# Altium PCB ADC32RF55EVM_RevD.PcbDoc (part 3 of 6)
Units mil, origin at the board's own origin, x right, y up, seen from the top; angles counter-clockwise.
Board outline 4190 x 2750 mil, 14 copper layers (Top Copper, Layer 2 (GND1), Layer 3 (PWR1), Layer 4 (GND2, Layer 5 (PWR2), Layer 6 (GND3), Layer 7 (SIG1), Layer 8 (GND4), Layer 9 (GND5), Layer 10 (SIG2), Layer 11 (GND6), Layer 12 (PWR3), Layer 13 (GND7), Bottom Copper), stack 58.6 mil thick; 427 components, 558 nets, 1902 pads, 1008 vias.
Unrouted connection lines stored in the file: 51.
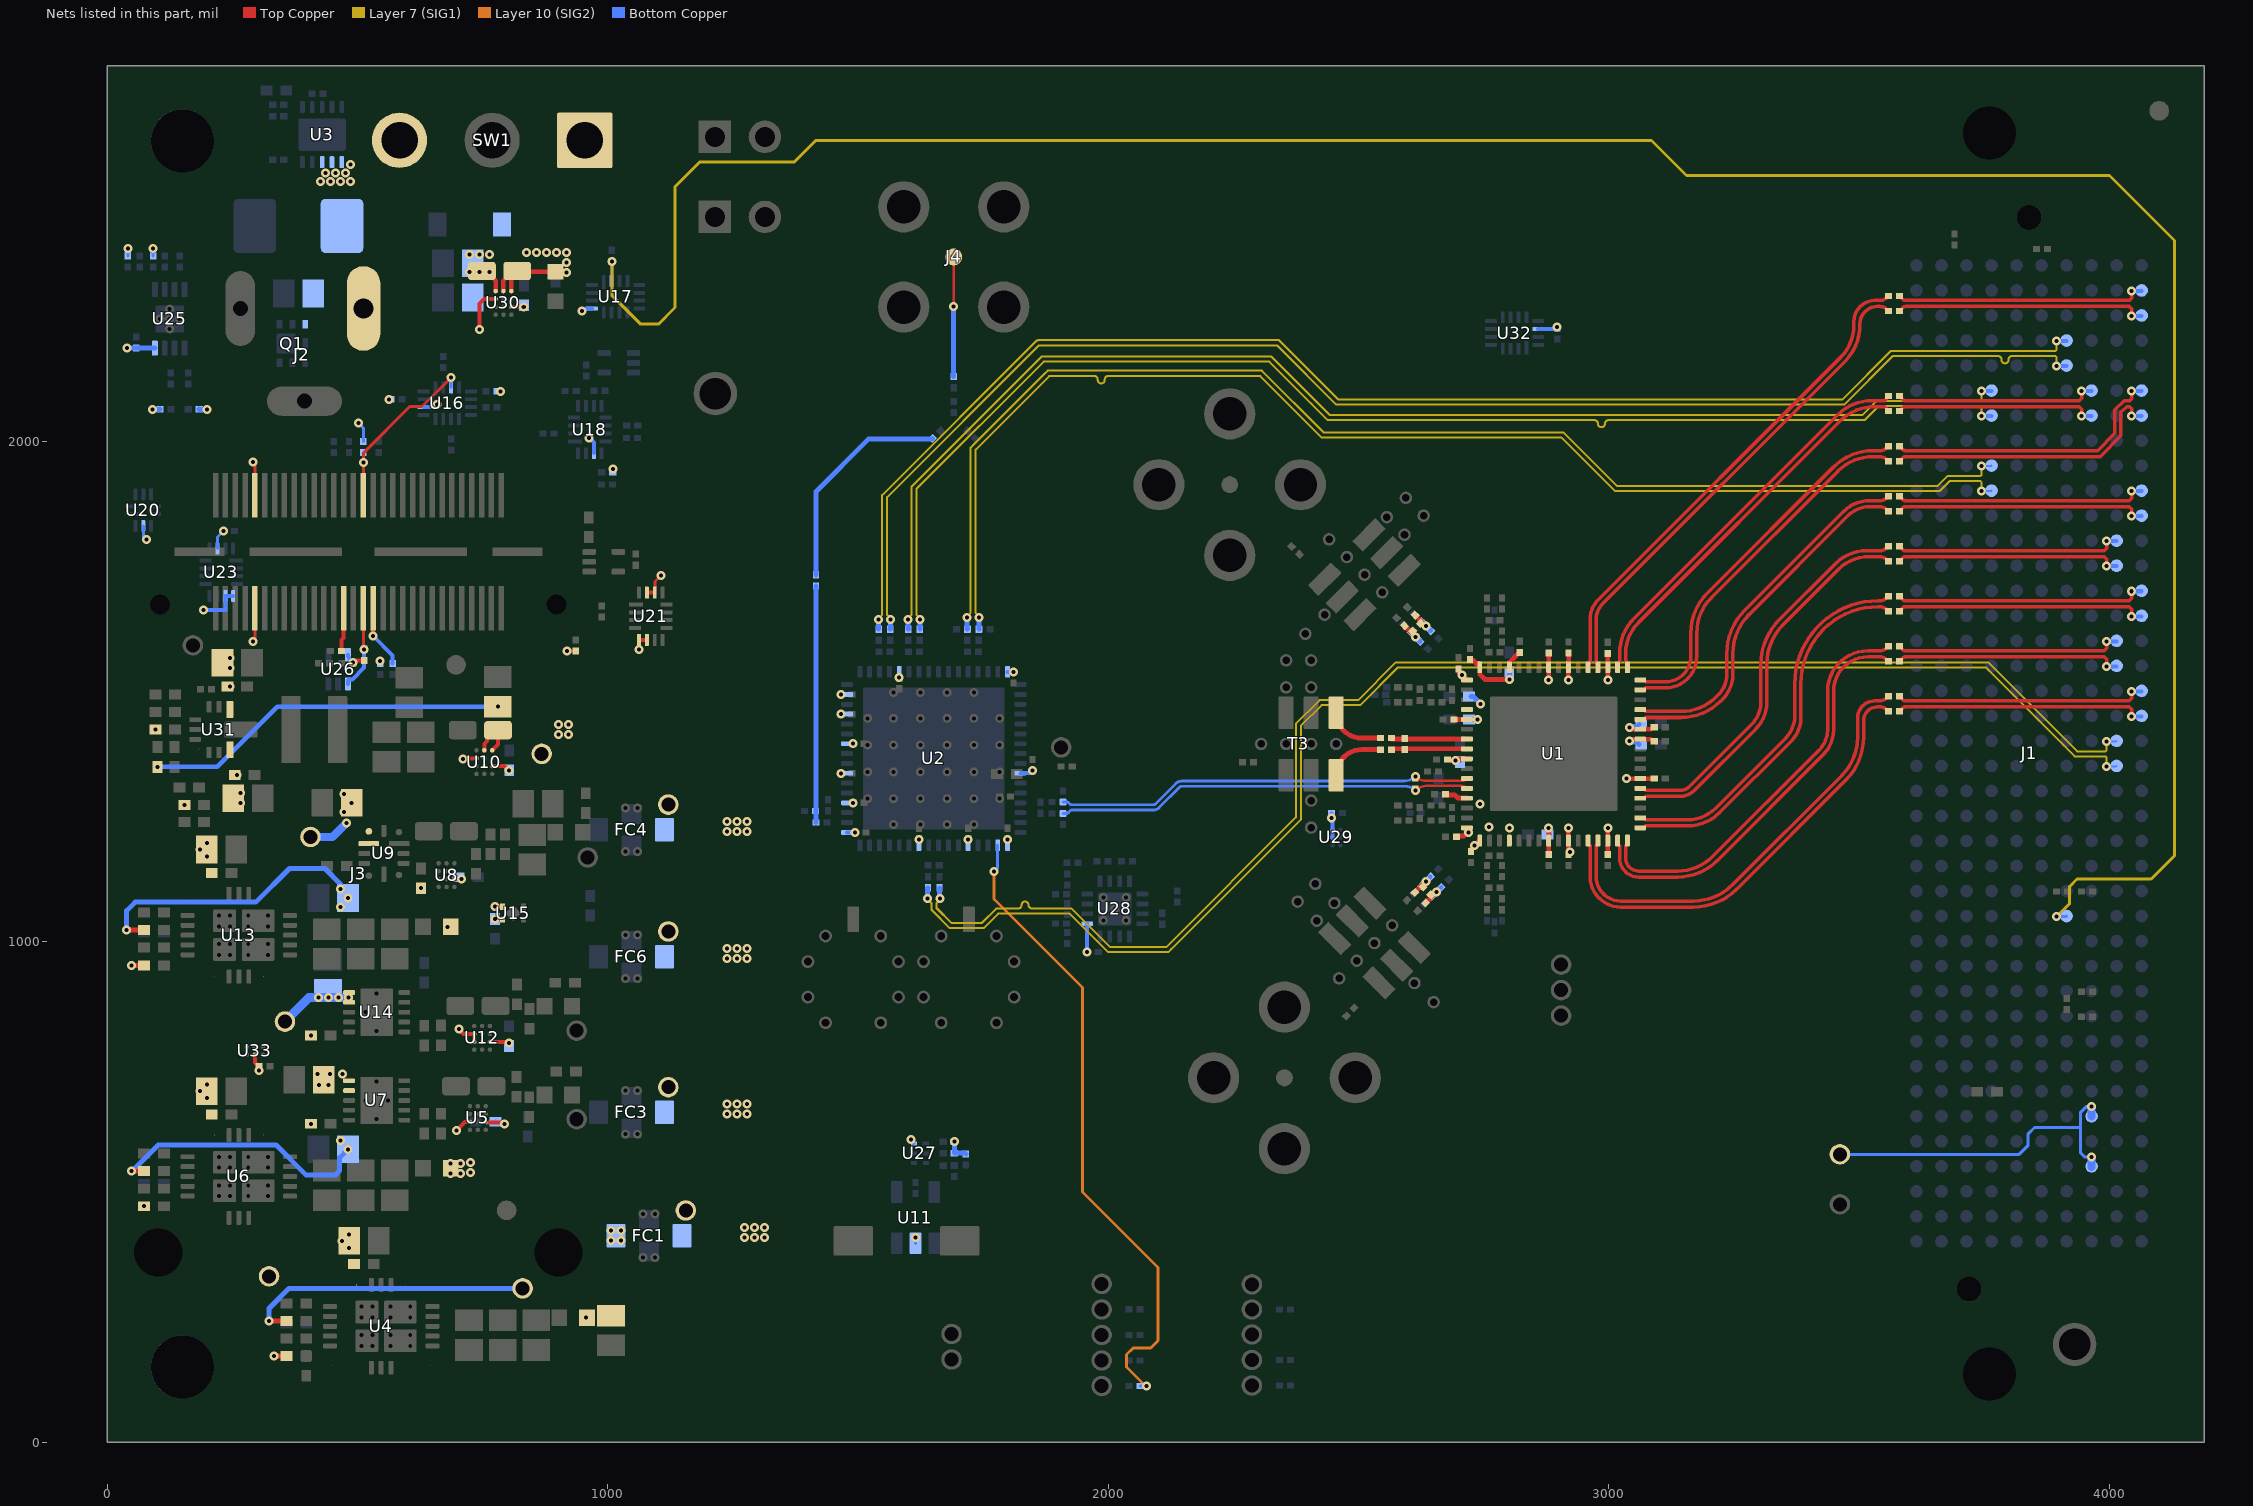
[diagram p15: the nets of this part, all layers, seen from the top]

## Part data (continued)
R24 R25 R28 R40 R41 R42 R43 R44 R47 R50 R51 R52 R53 R54 R56 R57 R63 R65 R66 R81 R83 R84 R85 R92 R93 R94 R95 R96 R154 R177: library part RSMD020100762, "RES SMD 10K OHM 1% 1/20W 0201", Manufacturer="Panasonic Electronic Components", Operating Temperature="-55°C ~ 125°C", Power (Watts)="0.05W, 1/20W", Resistance="10 kΩ", Supplier Part Number 1=P122414CT-ND, Temperature Coefficient=±200ppm/°C, Tolerance=±1%
R27: library part RSMD040200167, "RES SMD 1.4K OHM 0.1% 1/16W 0402", Manufacturer="Panasonic Electronic Components", Operating Temperature="-55°C ~ 155°C", Power (Watts)="0.063W, 1/16W", Ratings=AEC-Q200, Resistance="1.4 kΩ", Supplier Part Number 1=P1.4KDCCT-ND, Temperature Coefficient=±25ppm/°C, Tolerance=±0.1%
R29 R55 R67 R70 R71 R72 R73 R77 R91 R129 R133 R142 R146 R147 R149 R150 R157 R158 R160 R161: library part RSMD020101699, "RES SMD 0 OHM JUMPER 1/20W 0201", Manufacturer="Panasonic Electronic Components", Operating Temperature="-55°C ~ 125°C", Power (Watts)="0.05W, 1/20W", Resistance="0 Ω", Supplier Part Number 1=P15979CT-ND, Tolerance=Jumper
R30: library part RSMD040200009, "RES 1K OHM 0.1% 1/10W 0402", Manufacturer="Panasonic Electronic Components", Operating Temperature="-55°C ~ 155°C", Power (Watts)="0.1W, 1/10W", Ratings=AEC-Q200, Resistance="1 kΩ", Supplier Part Number 1=10-ERA-2VEB1001XCT-ND, Temperature Coefficient=±25ppm/°C, Tolerance=±0.1%
R36: library part RSMD040203879, "RES SMD 88.7K OHM 1% 1/10W 0402", Manufacturer="Panasonic Electronic Components", Operating Temperature="-55°C ~ 155°C", Power (Watts)="0.1W, 1/10W", Ratings=AEC-Q200, Resistance="88.7 kΩ", Supplier Part Number 1=P88.7KLCT-ND, Temperature Coefficient=±100ppm/°C, Tolerance=±1%
R37: library part RSMD040200541, "RES SMD 12.1KOHM 0.1% 1/16W 0402", Manufacturer="Panasonic Electronic Components", Operating Temperature="-55°C ~ 155°C", Power (Watts)="0.063W, 1/16W", Ratings=AEC-Q200, Resistance="12.1 kΩ", Supplier Part Number 1=10-ERA-2APB1212XCT-ND, Temperature Coefficient=±15ppm/°C, Tolerance=±0.1%
R45 R46 R48 R49 R58 R59 R60 R61 R62 R74 R88 R127 R128 R141 R162 R163: library part RSMD020100289, "RES SMD 100 OHM 1% 1/20W 0201", Manufacturer="Panasonic Electronic Components", Operating Temperature="-55°C ~ 125°C", Power (Watts)="0.05W, 1/20W", Resistance="100 Ω", Supplier Part Number 1=P122654CT-ND, Temperature Coefficient=±200ppm/°C, Tolerance=±1%
R64 R103 R104 R111 R118 R119 R126: library part RSMD020100143, "RES SMD 1K OHM 1% 1/20W 0201", Manufacturer="Panasonic Electronic Components", Operating Temperature="-55°C ~ 125°C", Power (Watts)="0.05W, 1/20W", Resistance="1 kΩ", Supplier Part Number 1=P122413CT-ND, Temperature Coefficient=±200ppm/°C, Tolerance=±1%
R68 R69 R82 R90 R97: library part RSMD020100606, "RES SMD 2.2K OHM 1% 1/20W 0201", Manufacturer="Panasonic Electronic Components", Operating Temperature="-55°C ~ 125°C", Power (Watts)="0.05W, 1/20W", Resistance="2.2 kΩ", Supplier Part Number 1=P122832CT-ND, Temperature Coefficient=±200ppm/°C, Tolerance=±1%
R80 R140: library part RSMD020100147, "RES SMD 220 OHM 1% 1/20W 0201", Manufacturer="Panasonic Electronic Components", Operating Temperature="-55°C ~ 125°C", Power (Watts)="0.05W, 1/20W", Resistance="220 Ω", Supplier Part Number 1=P122831CT-ND, Temperature Coefficient=±200ppm/°C, Tolerance=±1%
R99 R101 R106 R107 R108 R109 R113 R114 R115 R116 R121 R122 R123 R124 R131 R164: library part RSMD020101700, "Thick Film Resistors - SMD 8.66Ohms 1/20W 0201 1%", Manufacturer=Yageo, Operating Temperature="-55°C ~ 125°C", Power (Watts)="0.05W, 1/20W", Resistance="8.66 Ω", Supplier Part Number 1=13-RC0201FR-078R66LCT-ND, Temperature Coefficient="- 100 PPM / C, + 350 PPM / C", Tolerance=±1%
R102 R105 R110 R112 R117 R120 R125 R130: library part RSMD020100157, "RES SMD 140 OHM 1% 1/20W 0201", Manufacturer="Panasonic Electronic Components", Operating Temperature="-55°C ~ 125°C", Power (Watts)="0.05W, 1/20W", Resistance="140 Ω", Supplier Part Number 1=P122727CT-ND, Temperature Coefficient=±200ppm/°C, Tolerance=±1%
R132 R134 R135: library part RSMD020100063, "RES SMD 16 OHM 1% 1/20W 0201", Manufacturer="Panasonic Electronic Components", Operating Temperature="-55°C ~ 125°C", Power (Watts)="0.05W, 1/20W", Resistance="16 Ω", Supplier Part Number 1=P122773CT-ND, Temperature Coefficient=±200ppm/°C, Tolerance=±1%
R143 R144 R145: library part RSMD020100177, "RES SMD 49.9 OHM 1% 1/20W 0201", Manufacturer="Panasonic Electronic Components", Operating Temperature="-55°C ~ 125°C", Power (Watts)="0.05W, 1/20W", Resistance="49.9 Ω", Supplier Part Number 1=P123049CT-ND, Temperature Coefficient=±200ppm/°C, Tolerance=±1%
R148 R151 R152 R153 R159: library part RSMD020100132, "RES SMD 560 OHM 1% 1/20W 0201", Manufacturer="Panasonic Electronic Components", Operating Temperature="-55°C ~ 125°C", Power (Watts)="0.05W, 1/20W", Resistance="560 Ω", Supplier Part Number 1=P123075CT-ND, Temperature Coefficient=±200ppm/°C, Tolerance=±1%
R182: library part RSMD040200983, "RES SMD 17.4K OHM 1% 1/10W 0402", Manufacturer="Panasonic Electronic Components", Operating Temperature="-55°C ~ 155°C", Power (Watts)="0.1W, 1/10W", Ratings=AEC-Q200, Resistance="17.4 kΩ", Supplier Part Number 1=P17.4KLCT-ND, Temperature Coefficient=±100ppm/°C, Tolerance=±1%
SH-J7 SH-J8: library part cmp00093, "2 (1 x 2) Position Shunt Connector Black Closed Top 0.100\" (2.54mm) Gold", Alt Manufacturer=-, Manufacturer=Sullins, Supplier Part Number 1=S9001-ND
SW1: "Switch Slide SPDT 120V, 6A", Alt Manufacturer=-, Manufacturer="C&K Components", Supplier Part Number 1=CKN9628-ND
SW3: library part cmp00291, "SWITCH TACTILE SPST-NO 0.05A 12V", Alt Manufacturer=-, Manufacturer="Würth Elektronik", Supplier Part Number 1=732-7053-1-ND
T1 T2 T3: "1:2 CORE & WIRE Transformer, 10 to 3000 MHz, 50Ω", Alt Manufacturer=-, Manufacturer=Mini-Circuits, Supplier Part Number 1=3157-TCM2-33WX+CT-ND
TP3 TP4: library part cmp00041, "Test Point, Multipurpose, Black, TH", Alt Manufacturer=-, Color=Black, Manufacturer=Keystone, Supplier Part Number 1=36-5011-ND
U1: "Dual channel 14-bit 3.0 GSPS RF sampling data converter, RTD0064L (VQFN-64)", Alternate Manufacturer="Texas Instruments"
U2: "Ultra-low-noise, 3.2-GHz, 15-output, JESD204B clock jitter cleaner with dual loop", Alt Manufacturer="Texas Instruments", Alt PartNumber=LMK04832NKDT, Color=-, PartNumber=LMK04832NKDR
U3: library part cmp00157, "12V, 5A, 30mΩ eFuse with Adjustable +/-15% Accurate Current Limit, DRC0010J (VSON-10)", Alt Manufacturer=-, Manufacturer="Texas Instruments"
U4: library part cmp00201, "3-V to 17-V, 3-A Low-Noise and Low-Ripple Buck Power Module with Integrated Ferrite Bead Filter Compensation", Alt Manufacturer=-, Manufacturer="Texas Instruments", Max Supply Voltage=17V, Min Supply Voltage=3V, Nominal Supply Current=5mA, Operating Temperature Range="-55°C to +125°C", Output Voltage=0.8-5.5V, PartNumber=TPSM82913RDU, Switching Frequency=1/2.2MHz
U5 U8 U10 U12 U30: "28-V, 16-Bit, I2C Output Current, Voltage and Power Monitor With Alert in WCSP Package", Color=-, Manufacturer="Texas Instruments", PartNumber=INA231AIYFFT, Supplier Part Number 1=296-41263-1-ND
U6: "3-V to 17-V, 3-A Low-Noise and Low-Ripple Buck Power Module with Integrated Ferrite Bead Filter Compensation", Alt Manufacturer=-, Manufacturer="Texas Instruments", Max Supply Voltage=17V, Min Supply Voltage=3V, Nominal Supply Current=5mA, Operating Temperature Range="-55°C to +125°C", Output Voltage=0.8-5.5V, PartNumber=TPSM82913RDU, Switching Frequency=1/2.2MHz
U7 U14: library part cmp00169, "1-A, ultra-low noise, ultra-high PSRR, RF voltage regulator", Alt Manufacturer=-, Manufacturer="Texas Instruments", Supplier Part Number 1=296-TPS7A9401DSCRCT-ND
U9: "Vin 1.1V to 6.5V, 3A, Ultra-Low-Noise, High-PSRR, Low-Dropout Linear Regulator, RPS0012 (VQFN-12)", Manufacturer="Texas Instruments", Operating Temperature Range="-40 to 125 C", Rating=Catalog
U11: "Open Drain, 1.6V threshold, Nano Power, Wide VIN Voltage Detector with Programmable Delay", Alt Manufacturer=-, Manufacturer="Texas Instruments"
U13: "3-V to 17-V, 3-A Low-Noise and Low-Ripple Buck Power Module with Integrated Ferrite Bead Filter Compensation", Alt Manufacturer=-, Manufacturer="Texas Instruments", Max Supply Voltage=17V, Min Supply Voltage=3V, Nominal Supply Current=5mA, Operating Temperature Range="-55°C to +125°C", Output Voltage=0.8-5.5V, Part Number=TPSM82913RDUR, PartNumber=TPSM82913RDU, Switching Frequency=1/2.2MHz
U15: "500-mA high-PSRR low-IQ low-dropout (LDO) voltage regulator with enable (1.8V Fixed output)", Mfr_Name="Texas Instruments"
U16 U18 U32: "Low-Voltage 4-Bit 1-of-2 FET Multiplexer/Demultiplexe", Color=-, Manufacturer="Texas Instruments", PartNumber=SN74CBTLV3257RSVR, Supplier Part Number 1=296-35586-1-ND
U17 U21 U23: library part cmp00171, "Translation - Voltage Levels 4-bit dual-supply bus transceiver with 3-state outputs and independent direction control inputs", Alt Manufacturer="Texas Instruments", Alt PartNumber=SN74AXC4T774RSV, Color=-, Supplier Part Number 1=296-24741-1-ND
U19 U22: "Single Bus Buffer Gate With 3-State Outputs. Active high enable.", Alt Manufacturer=-, Manufacturer="Texas Instruments"
U20: library part cmp00300, "ESD-Protected, Low Capacitance, 2-Channel, 2:1 Switch, With Powered-off Protection", Alt Manufacturer=-, Manufacturer="Texas Instruments", PartNumber=TMUX154ERSWR
U25: library part cmp00154, "EEPROM 64K 8KX8 1.8V SER EE IND 1/4AWP RPO", Alt Manufacturer=-, Manufacturer=Microchip, Supplier Part Number 1=24LC64FT-I/MNYCT-ND
U26: library part cmp00472, "Single Bus Buffer Gate With 3-State Outputs", Alt Manufacturer=-, Manufacturer="Texas Instruments"
U27: library part cmp00518, "Low-Power Single 2-Input Positive-AND Gate", Color=-, Manufacturer="Texas Instruments", PartNumber=SN74AUP1G08DRYR, Supplier Part Number 1=296-SN74AUP1G08DRYRCT-ND
U28: library part cmp00271, "Texas Instruments", Color=-, Manufacturer_Part_Number=LMK1D1204RGTR, PartNumber=LMK1D1204RGTT, Supplier Part Number 1=296-LMK1D1204RGTRCT-ND
U29 U33: library part cmp00348, "±0.1°C accurate digital temperature sensor with integrated NV memory, YBG0006AJAP (DSBGA-6)", Alt Manufacturer=-, Manufacturer="Texas Instruments"
U31: library part cmp00293, "4-V to 18-V Input, 6-A Synchronous SWIFT™ Step-Down Converter with Internally Compensated Advanced Current Mode Control", Color=-, Manufacturer="Texas Instruments", Supplier Part Number 1=296-TPS543620RPYRCT-ND
ZZ1: library part cmp00107, "This Assembly Note is for PCB labels only", Alt Manufacturer=-
ZZ2: library part CMP-0077236-1
ZZ3: library part CMP-0077237-1
ZZ4: library part CMP-0077238-1

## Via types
v1: diameter 18, hole 8, Top Copper to Bottom Copper, tented both sides, 1004 vias
v2: diameter 25.75, hole 15.75, Top Copper to Bottom Copper, tented both sides, 4 vias

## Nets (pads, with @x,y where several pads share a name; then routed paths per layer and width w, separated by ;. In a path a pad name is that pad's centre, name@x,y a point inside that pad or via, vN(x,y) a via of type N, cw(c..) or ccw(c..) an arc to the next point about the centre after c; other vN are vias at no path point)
2p1V: C13.2 C14.2 C24.2 FB2.2 PP4.1 R14.2 U7.1 U7.2 U9.1 U9.2 | length 627.5
  Top Copper w10: v1(48.7,541.26) R14.2@73.7,541.26
  Bottom Copper w10: v1(48.7,541.26) 49.41,541.26 101.66,593.5 337.35,593.5 396.85,534 456,534 464.45,542.45 464.45,568.27 v1(481.1,584.92) ; v1(466.1,602.92) C24.2@466.1,606.9
  Bottom Copper w16: PP4.1@406,1209 450.33,1209 v1@478.11,1236.78
  other v1: 686.12,537 706.12,537 725.77,538.14 686.12,557 706.12,557 725.77,558.14 422.93,713.91 442.44,713.78 420.02,735.87 445.02,735.87 470.02,735.87 478.11,1237.25 473.32,1259.12 488.32,1277.12 473.32,1295.12
2p7V: C25.2 C28.2 C57.2 FB5.2 PP10.1 R34.2 U14.1 U14.2 U15.3 U15.4 | length 735.7
  Top Copper w8: v1(775,1045) ccw(c777.41,1047.41) 777.41,1044 U15.4@789.87,1044 ; v1(775,1070) ccw(c775.99,1070.99) 775.99,1069.59 U15.3@789.87,1069.59
  Top Copper w10: v1(38.7,1023.45) R34.2@73.7,1023.45
  Bottom Copper w10: v1(38.7,1023.45) 38.7,1061.7 55.62,1078.62 296.62,1078.62 363.95,1145.95 434.94,1145.95 466.1,1114.79 v1(466.1,1105.11)
  Bottom Copper w18: PP10.1@355,840 403.43,888.43 v1(422.43,888.43) v1(442.43,888.43) v1(462.43,888.43) v1(482.43,888.43)
  other v1: 680.12,1029.55 466.1,1069.11 481.1,1087.11
3p3V: C12.2 FB1.2 FC1.1 PP2.1 R6.2 | length 583.5
  Top Copper w10: v1(323.12,241.91) R6.2@358.12,241.91
  Bottom Copper w10: v1(323.12,241.91) 323.12,266.91 363.21,307 PP2.1@830,307
  other v1: 956.42,248.47 1006.45,402.39 1026.45,402.39 1006.45,422.39 1026.45,422.39
3p3V_Utility: C1.2 C18.2 C32.2 C40.2 C45.2 C51.2 C67.2 C132.2 C139.1 C140.1 C141.1 C142.1 C143.1 C144.1 C145.1 C146.1 C147.1 C148.1 C151.1 C152.1 C159.2 FC1.3 J3.51 J3.52 PP3.1 R23.2 R33.2 R40.1 R41.1 R65.2 R66.2 R68.2 R69.2 R81.1 R82.2 R84.2 R90.2 R92.1 R93.1 R97.2 R100.2 R155.2 R177.1 U2.10 U2.17 U2.21 U2.26 U2.33 U2.36 U2.39 U2.42 U2.45 U2.47 U2.53 U2.64 U5.B1 U5.B3 U8.B1 U10.B1 U10.C3 U12.B1 U12.B3 U12.C3 U16.14 U17.13 U18.14 U20.9 U21.5 U21.6 U21.14 U21.15 U23.5 U23.6 U23.14 U25.8 U26.5 U28.5 U29.B1 U29.C1 U30.B1 U30.C3 U32.14 U33.B1 | length 1300.4
  Top Copper w6: v1(290.89,1599.27) 290.89,1602.52 295.06,1606.69 J3.52@295.06,1666 ; v1(290.89,1958.32) 290.89,1955.07 295.06,1950.91 J3.51@295.06,1891.59 ; v1(919,1581) 935.91,1581 R84.2@936.21,1580.71 ; U21.14@1093.87,1697.24 1094.46,1697.83 1094.46,1719.46 v1(1106,1731)
  Top Copper w8: U33.B1@294.75,774 294.95,773.8 294.95,758.26 302.21,751 C159.2@303,751 ; v1(490.77,1557.46) 493.34,1557.46 497.91,1562.02 R82.2@513.27,1562.02 ; U8.B1@693.68,1124.89 693.73,1124.83 v1(707.63,1124.78) v1(707.63,1124.78) ; v1(698.01,622.42) 715.05,639.46 724.53,639.46 U5.B3@724.7,639.62 ; v1(702.34,825.49) 712.25,815.58 U12.C3@733.13,815.58 U12.B3@733.13,799.83 ; v1(711,1365) 712.29,1366.29 737.52,1366.29 U10.C3@737.68,1366.46 ; v1(744,2223) 744,2275 753.09,2284.09 U30.C3@775.93,2284.09 ; U5.B1@756.19,638.62 791.26,638.62 v1(794.18,635.7) ; U12.B1@764.63,799.83 799.69,799.83 v1(802.61,796.91) ; U10.B1@769.18,1350.71 793.28,1350.71 801.69,1342.3 v1(803.14,1342.3) ; U30.B1@807.43,2268.35 v1@832.16,2268.35 ; v1(1062.31,1583.8) 1062.38,1583.87 U21.5@1062.38,1602.76 U21.6@1078.13,1602.76 ; U21.15@1078.13,1697.24 U21.14@1093.87,1697.24
  Top Copper w9: v1(832.16,2268.13) v1@832.16,2268.35
  Bottom Copper w6: v1(40.96,2384.84) v1(40.96,2384.84) R92.1@41.04,2370.29 ; U20.9@72,1830.5 72,1808.19 77.15,1803.05 v1(78.8,1803.05) ; v1(91.67,2384.92) 91.67,2370.33 R93.1@91.79,2370.21 ; U23.14@220.13,1785.24 220.13,1808.43 v1(232.05,1820.35) v1(232.05,1820.35) ; v1(501.97,2035.89) 511.71,2026.15 R40.1@511.71,1999.47
  Bottom Copper w8: v1(192.24,1662.47) 235.87,1662.47 U23.6@235.87,1690.76 U23.5@251.62,1690.76 ; U26.5@481,1573 ccw(c494.93,1573) 485.08,1563.15 v1(490.77,1557.46) ; U16.14@632,2067.94 653.94,2067.94 v1(659,2073) ; C32.2@701.86,1128.42 705.49,1124.78 v1(707.63,1124.78) ; C18.2@775.48,640.01 777.38,638.11 792.27,638.11 v1@794.18,636.2 ; v1(832.16,2268.13) 832.43,2268.13 C1.2@832.43,2271.35 ; v1(948.38,2259.85) 951.08,2259.85 956.08,2264.85 U17.13@968.38,2264.85 ; v1(963,2006) 972.19,1996.81 U18.14@972.19,1975.91 ; U2.33@1478.09,1218.19 1478.18,1218.09 1493.72,1218.09 v1(1493.81,1218) ; U2.64@1798.95,1539.05 v1(1810.76,1539.05) ; U2.10@1824.54,1336.3 1825.46,1337.22 1841.93,1337.22 1846.13,1341.42 v1(1848.83,1341.42) ; v1(1957.98,979) U28.5@1957.95,1035.8 ; v1(2445.77,1247.24) v1@2445.95,1247.24 ; C132.2@2445.77,1256.24 2445.77,1247.42 v1@2445.95,1247.24 ; U29.B1@2448.25,1208 U29.C1@2448.25,1223.75 2448.25,1244.94 v1@2445.95,1247.24 ; U32.14@2859.24,2223.87 2894.7,2223.87 2897,2226.17 v1(2897,2228)
  Bottom Copper w10: v1(39,2186) C67.2@58.2,2185.98 94.98,2185.98 U25.8@95.16,2185.8 ; v1(89.96,2063.53) 104.98,2063.53 R68.2@104.98,2063.76 ; R69.2@183.76,2063.76 183.76,2063.53 v1(198.78,2063.53)
  other v1: 1273.31,409.08 1293.31,409.08 1313.31,409.08 1273.31,429.08 1293.31,429.08 1313.31,429.08 406.92,635.87 302.89,742.29 406.92,812.12 627.1,1106.58 1621.79,1204.41 1720.21,1204.41 1798.95,1204.41 1489.9,1277.24 1466.28,1336.3 1489.9,1395.35 96.09,1423.5 1466.28,1454.41 1466.28,1493.78 1582.42,1527.24 544.93,1560.6 1010.59,1944.3 562.86,2083.21 785.62,2098.91
12V: C7.2 C8.2 C19.2 C20.2 C52.2 C53.2 C165.2 C166.2 C177.2 C178.2 D3.1 PP1.1 R1.2 R5.1 R11.1 R31.1 R76.2 U4.18 U6.18 U13.18 U30.D1 U30.D2 U31.8 U31.12 | length 228.5
  Top Copper w9: U30.D2@791.68,2299.84 791.68,2320.9 810.78,2340 R1.2@819.04,2340 ; U30.D1@807.43,2299.84 807.43,2328.39 R1.2@819.04,2340 ; D3.1@895.56,2338.31 820.73,2338.31 R1.2@819.04,2340
  Top Copper w10: v1(48.7,952.51) R31.1@73.7,952.51 ; v1(333.12,171.91) R5.1@358.12,171.91
  other v1: 483.38,387.75 469.49,401.45 483.38,414.79 73.7,471.26 198.95,687.5 185.06,701.21 198.95,714.55 198.95,1170.29 185.06,1184 198.95,1197.34 154.15,1272.74 266.65,1276.5 266.65,1296.5 259.5,1333.2 244.93,1509.85 245.09,1546.9 245.09,1566.9 918,2337 918,2357 838,2377 858,2377 878,2377 898,2377 918,2377
12V_FMC: J1.C35 J1.C37 PP29.1 SW1.1 | length 689.6
  Bottom Copper w6: PP29.1@3462,575 3820.29,575 3838.32,593.03 3838.32,615.8 3850.84,628.32 3943,628.32 ; v1(3965,570) 3950.52,570 3943,577.52 3943,628.32 ; v1(3965,670) 3954,670 3943,659 3943,628.32
  Bottom Copper w16: J1.C37@3965,550 v1(3965,570) ; J1.C35@3965,650 v1(3965,670)
12V_Plug: C2.1 D1.2 J2.1 Q1.3 SW1.3
12V_VIN+: C3.1 C4.1 D2.1 R1.1 U3.6 U3.7 U3.8 U30.D3 | length 66.8
  Top Copper w9: R1.1@738.94,2338 740.94,2340 R1.1@748.57,2340 756.83,2340 775.93,2320.9 U30.D3@775.93,2299.84
  other v1: 723.94,2338 743.94,2338 763.94,2338 723.94,2373 743.94,2373 763.94,2373 426,2519 446,2519 466,2519 486,2519 436,2536 456,2536 476,2536 486,2553
ADC_SYSREF_N: R74.2 R146.1 R150.1 U1.28 | length 836.4
  Top Copper w5: v1(2613.77,1301.92) cw(c2635.56,1280.14) 2635.56,1310.94 2705.08,1310.94 cw(c2705.08,1294.41) U1.28@2716.77,1306.1
  Bottom Copper w5.5: R146.1@1909.59,1255.9 1916.36,1255.9 ccw(c1916.36,1261.4) 1920.23,1257.49 1924.04,1261.3 cw(c1927.92,1257.4) 1927.92,1262.9 2090.47,1262.9 ccw(c2090.47,1278.9) 2101.73,1267.53 2101.78,1267.58 2142.87,1308.68 cw(c2146.75,1304.77) 2146.75,1310.27 2574.27,1310.27 2593.62,1310.27 cw(c2593.62,1281.77) v1(2613.77,1301.92) ; v1@2615.27,1303.42 v1@2616.77,1301.92
ADC_SYSREF_P: R74.1 R147.1 R149.1 U1.27 | length 835.2
  Top Copper w5: v1(2613.77,1329.97) ccw(c2635.56,1351.75) 2635.56,1320.94 2705.08,1320.94 ccw(c2705.08,1337.48) U1.27@2716.77,1325.79
  Bottom Copper w5.5: R147.1@1909.59,1278.9 1913.93,1278.9 1917.15,1278.9 cw(c1917.15,1273.4) 1921.04,1277.29 1923.34,1274.99 ccw(c1927.21,1278.9) 1927.21,1273.4 2090.47,1273.4 ccw(c2090.47,1278.9) 2094.34,1274.99 2135.43,1316.08 2135.49,1316.14 cw(c2146.75,1304.77) 2146.75,1320.77 2591.56,1320.77 ccw(c2591.56,1352.18) v1(2613.77,1329.97) cw(c2612.03,1329.97) v1@2613.26,1328.74
AVDD12: C114.2 C115.2 C116.2 C117.2 C118.2 C119.2 FC4.3 PP8.1 U1.13 U1.16 U1.21 U1.33 U1.36 | length 235.7
  Top Copper w10: C116.2@2691.05,1443.9 2733.89,1443.9 2735.83,1441.96 v1@2737.99,1441.96 ; C117.2@2723.71,1563.53 2723.71,1561.99 2724.26,1561.44 2729.9,1561.44 2736.3,1555.04 U1.16@2742.28,1555.04 ; C118.2@2725,1180 2725,1184.41 v1(2732.36,1191.77) 2741.87,1201.28 2741.87,1203.42 2742.36,1202.94 U1.33@2742.36,1201.77 ; 2742.59,1534.09 2752.68,1524 v1(2801.43,1524) ; U1.13@2801.42,1548.23 2801.42,1557.42 2819.91,1575.91 2820.7,1575.91 2822,1577.21 C119.2@2822,1578
  Bottom Copper w10: C114.2@2721.06,1443.96 v1(2737.99,1443.96) ; v1(2801.43,1524) C115.2@2801.43,1537.94
  other v1: 1238.31,1220.07 1258.31,1220.07 1278.31,1220.07 2801.42,1226.87 2761,1229 1238.31,1240.07 1258.31,1240.07 1278.31,1240.07
AVDD18: C109.2 C110.2 C111.2 C112.2 C113.2 C160.2 FC6.3 PP12.1 R24.1 R25.1 R28.1 U1.17 U1.20 U1.29 U1.32 U1.58 U11.2 U27.6 | length 294.8
  Top Copper w9: v1@3041.02,1404.53 U1.58@3063.23,1404.53 3084.18,1404.53 3088.5,1400.21 C112.2@3091.01,1400.21
  Top Copper w10: C113.2@2674,1294.5 2675.3,1293.2 2692.27,1293.2 2699.06,1286.42 U1.29@2716.77,1286.42 ; C160.2@2695.94,1209.72 2697.24,1211.02 2710.02,1211.02 ; C111.2@2700,1545 2700,1539.41 v1(2706.77,1532.64) U1.17@2716.77,1522.64 ; U1.20@2710.04,1463.58 U1.20@2716.77,1463.58 ; U1.32@2716.77,1227.36 2717.57,1227.36 2717.65,1227.28 2717.65,1220.88 v1(2720.09,1218.44) 2717.93,1218.44 v1@2713.93,1214.44 ; 2710.02,1211.02 2713.44,1214.44 v1@2713.93,1214.44 ; 2710.02,1211.02 2710.51,1211.02 v1@2713.93,1214.44
  Bottom Copper w6: v1(1606.42,604.13) 1606.42,600.89 1608.83,598.48 1608.83,597.54 1609.77,596.6 U27.6@1611.74,596.6 ; U11.2@1614.9,397.14 1614.9,408.9 v1(1615,409)
  Bottom Copper w10: v1(1692.41,600.26) R25.1@1692.41,577.26 1714.11,577.26 1715.41,575.96 R28.1@1715.41,575.26 ; C109.2@2725,1490 2728.94,1490 v1(2744,1474.96) ; v1(3042,1400.51) 3043.53,1398.98 3056.02,1398.98 C110.2@3061,1394
  other v1: 1238.31,966.58 1258.31,966.58 1278.31,966.58 1238.31,986.58 1258.31,986.58 1278.31,986.58 2743,1275
ChA_SPLIT_N: C70.2 R99.1 R103.2 R113.1 | length 56.6
  Top Copper w10: C70.2@2592.04,1631.03 v1(2614.08,1609)
  Bottom Copper w10: R113.1@2605.09,1617.99 R99.1@2623.09,1599.99
ChA_SPLIT_P: C73.2 R103.1 R106.1 R108.1 | length 56.6
  Top Copper w10: C73.2@2613.26,1652.25 v1(2635.3,1630.2)
  Bottom Copper w10: R108.1@2626.3,1639.2 v1(2635.3,1630.2) R106.1@2644.3,1621.2
ChB_SPLIT_N: C81.2 R115.1 R118.1 R123.1 | length 56.6
  Top Copper w10: C81.2@2612.75,1098.26 v1(2634.8,1120.3)
  Bottom Copper w9: R123.1@2625.8,1111.3 v1(2634.8,1120.3) R115.1@2643.8,1129.3
ChB_SPLIT_P: C99.2 R118.2 R121.1 R131.1 | length 56.6
  Top Copper w10: C99.2@2633.97,1077.04 2647.5,1090.58 v1(2656,1099.08)
  Bottom Copper w9: R131.1@2647.01,1090.09 R121.1@2665.01,1108.09
CLK_ADC_N: C153.2 R13.2 U1.24 | length 150.8
  Top Copper w9: C153.2@2566,1384.84 U1.24@2716.77,1384.84
CLK_ADC_P: C106.2 R13.1 U1.23 | length 150.8
  Top Copper w10: C106.2@2566,1404.53 U1.23@2716.77,1404.53
CLK_LMK: C105.1 R135.2 | length 443
  Bottom Copper w10: C105.1@1416.04,1732.92 1416.04,1899.04 1521.48,2004.48 1648.49,2004.48 R135.2@1649.05,2005.03
CLK_TX_N: C153.1 T3.4 | length 117.7
  Top Copper w10: T3.4@2455.51,1332.26 cw(c2506.74,1332.26) 2506.74,1383.49 C153.1@2543.95,1383.49
CLK_TX_P: C106.1 T3.3 | length 117.4
  Top Copper w10: T3.3@2455.51,1457.46 ccw(c2506.29,1457.46) 2506.29,1406.69 C106.1@2543.95,1406.69
CLKIN1_P: C105.2 C107.2 R145.2 | length 473
  Bottom Copper w10: C107.2@1416.04,1237.87 1416.04,1260.87 C105.2@1416.04,1710.87
CLKVDD: C120.2 C121.2 FC3.3 PP6.1 U1.25 | length 49
  Top Copper w10: C121.2@2679,1364 2680,1363 2693,1363 v1(2694,1362) 2695.62,1362 2698.78,1365.16 U1.25@2716.77,1365.16
  Bottom Copper w10: v1(2694,1362) C120.2@2703.09,1362
  other v1: 1238.31,655.33 1258.31,655.33 1278.31,655.33 1238.31,675.33 1258.31,675.33 1278.31,675.33
CSb_LMK: R46.2 U2.18 | length 1295.7
  Layer 10 (SIG2) w6: v1(1772,1140) 1772,1084.79 1773.73,1083.06 1948.58,908.21 1948.58,499.42 2099.26,348.74 2099.26,202.43 2084.9,188.07 2050,188.07 2036.73,174.8 2036.73,149.74 2074.41,112.06 v1(2076.34,112.05)
  Bottom Copper w6: v1(1772,1140) 1779.27,1147.27 U2.18@1779.27,1192.6 ; R46.2@2063.67,112.05 v1(2076.34,112.05)
CSb_LMK_FMC: J1.D27 R47.2 U17.2 | length 5185.3
  Layer 7 (SIG1) w6: v1(1008.25,2359.22) 1008.25,2291.26 1065.78,2233.74 1101.38,2233.74 1134.55,2266.91 1134.55,2508.29 1184.26,2558 1373,2558 1415.57,2600.57 3085.35,2600.57 3155.4,2530.52 4000.8,2530.52 4130.47,2400.85 4130.47,1171.47 4084,1125 3935.79,1125 3921,1110.21 3921,1076 v1(3895,1050)
  Bottom Copper w6: U17.2@1008.25,2320.23 v1(1008.25,2359.22) ; v1(3895,1050) 3915,1050 J1.D27@3915,1051
CSb_LMK_USB: J3.29 R40.2 U16.3 | length 362.6
  Top Copper w6: J3.29@511.59,1891.59 511.59,1957.31 512.38,1958.1 512.38,1976.81 604.65,2069.08 628.89,2069.08 v1(687.12,2127.31)
  Bottom Copper w6: v1(511.71,1957.42) R40.2@511.71,1977.42 ; U16.3@687.12,2107.31 v1(687.12,2127.31)
DOUT0_ADC_N: C85.1 U1.5 | length 1000.3
  Top Copper w7: U1.5@2958.9,1548.23 2958.9,1555.12 2962.74,1558.96 2962.74,1575.51 2962.74,1643.32 cw(c3019.21,1643.32) 2979.24,1683.21 cw(c3019.21,1643.32) 2979.28,1683.25 3463.11,2167.08 ccw(c3398.19,2232) 3490,2232 3490,2239.1 cw(c3531.9,2239.1) 3531.9,2281 3541.62,2281 ccw(c3541.62,2301.3) 3555.44,2286.43 ccw(c3541.62,2301.3) 3555.97,2286.94 C85.1@3559.03,2290
DOUT0_ADC_P: C84.1 U1.4 | length 979.3
  Top Copper w7: U1.4@2978.58,1548.23 2978.58,1555.12 2974.74,1558.96 2974.74,1575.51 2974.74,1643.32 cw(c3019.21,1643.32) 2987.72,1674.72 cw(c3019.21,1643.32) 2987.77,1674.77 3471.59,2158.59 ccw(c3398.19,2232) 3502,2232 3502,2234.13 cw(c3536.87,2234.13) 3536.87,2269 3541.62,2269 cw(c3541.62,2248.71) 3555.44,2263.57 cw(c3541.62,2248.71) 3555.97,2263.06 C84.1@3559.03,2260
DOUT0_FMC_N: C85.2 J1.A2 | length 503.4
  Top Copper w7: C85.2@3581.07,2290 3587.83,2283.24 ccw(c3593.21,2288.62) 3593.21,2281.01 3975,2281 4040,2281 4045,2286 v1(4045,2300)
  Bottom Copper w8: v1(4045,2300) J1.A2@4065,2300
DOUT0_FMC_P: C84.2 J1.A3 | length 503.4
  Top Copper w7: C84.2@3581.07,2260 3587.83,2266.76 cw(c3593.21,2261.39) 3593.21,2268.99 3970.02,2268.99 ; 3970.03,2269 4040,2269 4045,2264 v1(4045,2250)
  Bottom Copper w8: v1(4045,2250) J1.A3@4065,2250
DOUT1_ADC_N: C87.1 U1.2 | length 796.1
  Top Copper w7: U1.2@3017.95,1548.23 3017.95,1555.12 3021.8,1558.96 3021.8,1575.51 cw(c3121.4,1575.51) 3050.97,1645.94 3457.51,2052.49 cw(c3526.36,1983.64) 3526.36,2081 3551.34,2081 3555.44,2085.1 3555.44,2087.2 3558.24,2090 C87.1@3559.03,2090
DOUT1_ADC_P: C86.1 U1.1 | length 776.7
  Top Copper w7: U1.1@3037.64,1548.23 3037.64,1555.12 3033.8,1558.96 3033.8,1575.51 cw(c3121.4,1575.51) 3059.45,1637.45 3461.71,2039.71 cw(c3532.42,1969) 3532.42,2069 3551.34,2069 3555.44,2064.9 3555.44,2062.8 3558.24,2060 C86.1@3559.03,2060
DOUT1_FMC_N: C87.2 J1.C6 | length 403.4
  Top Copper w7: C87.2@3581.07,2090 3587.83,2083.24 ccw(c3593.21,2088.62) 3593.21,2081.01 3940,2081 3945,2086 v1(3945,2100)
  Bottom Copper w8: v1(3945,2100) J1.C6@3965,2100
DOUT1_FMC_P: C86.2 J1.C7 | length 403.4
  Top Copper w7: C86.2@3581.07,2060 3587.83,2066.76 cw(c3593.21,2061.39) 3593.21,2068.99 3870.01,2068.99 ; 3870.03,2069 3940,2069 3945,2064 v1(3945,2050)
  Bottom Copper w8: v1(3945,2050) J1.C7@3965,2050
DOUT2_ADC_N: C89.1 U1.64 | length 744.6
  Top Copper w7: U1.64@3063.23,1522.64 3070.12,1522.64 3073.96,1518.8 3090.51,1518.8 3113.06,1518.8 ccw(c3113.06,1569.74) 3113.12,1518.8 ccw(c3113.06,1569.74) 3164,1569.74 3164,1616.58 cw(c3276,1616.58) 3196.8,1695.77 3449.23,1948.2 cw(c3528.42,1869) 3449.26,1948.24 cw(c3528.42,1869) 3528.42,1981 3541.62,1981 ccw(c3541.62,2001.3) 3555.44,1986.43 ccw(c3541.62,2001.3) 3555.97,1986.94 C89.1@3559.02,1990
DOUT2_ADC_P: C88.1 U1.63 | length 744.7
  Top Copper w7: U1.63@3063.23,1502.95 3070.12,1502.95 3073.96,1506.8 3090.51,1506.8 3113.03,1506.8 ccw(c3113.03,1569.76) 3113.12,1506.8 ccw(c3113.03,1569.76) 3176,1569.76 3176,1616.58 cw(c3276,1616.58) 3205.29,1687.29 3458.09,1940.09 cw(c3527.88,1870.31) 3527.88,1969 3541.62,1969 cw(c3541.62,1948.71) 3555.44,1963.57 cw(c3541.62,1948.71) 3555.97,1963.06 C88.1@3559.02,1960
DOUT2_FMC_N: C89.2 J1.A6 | length 572.9
  Top Copper w7: C89.2@3581.07,1990 3587.83,1983.24 ccw(c3593.21,1988.62) 3593.21,1981.01 3977.12,1981 4011.5,2015.38 4011.5,2062.37 4030.13,2081 4040.9,2081 4045,2085.1 v1(4045,2100)
  Bottom Copper w8: v1(4045,2100) J1.A6@4065,2100
DOUT2_FMC_P: C88.2 J1.A7 | length 572.9
  Top Copper w7: C88.2@3581.07,1960 3587.83,1966.76 cw(c3593.21,1961.39) 3593.21,1968.99 3982.09,1969 4023.5,2010.41 4023.5,2057.4 4035.1,2069 4040.9,2069 4045,2064.9 v1(4045,2050)
  Bottom Copper w8: v1(4045,2050) J1.A7@4065,2050
DOUT3_ADC_N: C93.1 U1.61 | length 727.5
  Top Copper w7: U1.61@3063.23,1463.58 3070.12,1463.58 3073.96,1459.74 3090.51,1459.74 3144.32,1459.74 ccw(c3144.32,1559.74) 3215.03,1489.03 ccw(c3177.55,1533.88) 3236,1533.88 3236,1575 cw(c3359.05,1575) 3272.07,1662.04 3469.51,1859.49 cw(c3521.46,1807.54) 3521.46,1881 3541.62,1881 ccw(c3541.62,1901.3) 3555.44,1886.43 ccw(c3541.62,1901.3) 3555.97,1886.94 C93.1@3559.03,1890
DOUT3_ADC_P: C90.1 U1.60 | length 727.5
  Top Copper w7: U1.60@3063.23,1443.9 3070.12,1443.9 3073.96,1447.74 3090.51,1447.74 3144.32,1447.74 ccw(c3144.32,1559.74) 3223.51,1480.54 ccw(c3177.99,1533.73) 3248,1533.73 3248,1575 cw(c3359.05,1575) 3280.55,1653.55 3478,1851 cw(c3521.46,1807.54) 3521.46,1869 3541.62,1869 cw(c3541.62,1848.71) 3555.44,1863.57 cw(c3541.62,1848.71) 3555.97,1863.06 C90.1@3559.03,1860
DOUT3_FMC_N: C93.2 J1.A10 | length 503.4
  Top Copper w7: C93.2@3581.07,1890 3587.83,1883.24 ccw(c3593.21,1888.62) 3593.21,1881.01 3975,1881 4040,1881 4045,1886 v1(4045,1900)
  Bottom Copper w8: v1(4045,1900) J1.A10@4065,1900
DOUT3_FMC_P: C90.2 J1.A11 | length 503.4
  Top Copper w7: C90.2@3581.07,1860 3587.83,1866.76 cw(c3593.21,1861.39) 3593.21,1868.99 4040,1869 4045,1864 v1(4045,1850)
  Bottom Copper w8: v1(4045,1850) J1.A11@4065,1850
DOUT4_ADC_N: C95.1 U1.44 | length 915.4
  Top Copper w7: U1.44@2958.9,1201.77 2958.9,1194.88 2962.74,1191.04 2962.74,1130.26 ccw(c3024,1130.26) 3024,1069 3169.23,1069 ccw(c3169.23,1191.57) 3255.87,1104.87 ; 3255.9,1104.9 3473.81,1322.81 ccw(c3388.15,1408.47) 3473.85,1322.85 ccw(c3388.15,1408.47) 3509.29,1408.47 3509.29,1441.42 cw(c3536.87,1441.42) 3536.87,1469 3541.62,1469 cw(c3541.62,1448.71) 3555.44,1463.57 cw(c3541.62,1448.71) 3555.97,1463.06 C95.1@3559.03,1460
DOUT4_ADC_P: C94.1 U1.45 | length 898.7
  Top Copper w7: U1.45@2978.58,1201.77 2978.58,1194.88 2974.74,1191.04 2974.74,1130.26 ccw(c3024,1130.26) 3024,1081 3169.23,1081 ccw(c3169.23,1191.57) 3247.38,1113.35 ; 3247.41,1113.38 3465.33,1331.3 ; 3465.36,1331.33 ccw(c3388.15,1408.47) 3497.29,1408.47 3497.29,1446.39 cw(c3531.9,1446.39) 3531.9,1481 3541.62,1481 ccw(c3541.62,1501.3) 3555.44,1486.43 ccw(c3541.62,1501.3) 3555.97,1486.94 C94.1@3559.03,1490
DOUT4_FMC_N: C95.2 J1.A19 | length 503.4
  Top Copper w7: C95.2@3581.07,1460 3587.83,1466.76 cw(c3593.21,1461.39) 3593.21,1468.99 3970.03,1469 4040,1469 4045,1464 v1(4045,1450)
  Bottom Copper w8: v1(4045,1450) J1.A19@4065,1450
DOUT4_FMC_P: C94.2 J1.A18 | length 503.4
  Top Copper w7: C94.2@3581.07,1490 3587.83,1483.24 ccw(c3593.21,1488.62) 3593.21,1481.01 3975,1481 4040,1481 4045,1486 v1(4045,1500)
  Bottom Copper w8: v1(4045,1500) J1.A18@4065,1500
DOUT5_ADC_N: C97.1 U1.47 | length 845.2
  Top Copper w7: U1.47@3017.95,1201.77 3017.95,1194.88 3021.8,1191.04 3021.8,1167.2 ccw(c3060,1167.2) 3060,1129 3137.58,1129 ccw(c3137.58,1241) 3216.77,1161.8 3429.2,1374.23 ccw(c3380.7,1422.72) 3449.28,1422.72 3449.28,1499.94 cw(c3518.34,1499.94) 3518.34,1569 3541.62,1569 cw(c3541.62,1548.71) 3555.44,1563.57 cw(c3541.62,1548.71) 3555.97,1563.06 C97.1@3559.03,1560
DOUT5_ADC_P: C96.1 U1.48 | length 826.4
  Top Copper w7: U1.48@3037.64,1201.77 3037.64,1194.88 3033.8,1191.04 3033.8,1167.2 ccw(c3060,1167.2) 3060,1141 3137.58,1141 ccw(c3137.58,1241) 3208.29,1170.29 3420.71,1382.71 ccw(c3380.7,1422.72) 3437.28,1422.72 3437.28,1499.94 cw(c3518.34,1499.94) 3518.34,1581 3541.62,1581 ccw(c3541.62,1601.3) 3555.44,1586.43 ccw(c3541.62,1601.3) 3555.97,1586.94 C96.1@3559.03,1590
DOUT5_FMC_N: C97.2 J1.B17 | length 453.4
  Top Copper w7: C97.2@3581.07,1560 3587.83,1566.76 cw(c3593.21,1561.39) 3593.21,1568.99 3920.03,1569 3990,1569 3995,1564 v1(3995,1550)
  Bottom Copper w8: v1(3995,1550) J1.B17@4015,1550
DOUT5_FMC_P: C96.2 J1.B16 | length 453.4
  Top Copper w7: C96.2@3581.07,1590 3587.83,1583.24 ccw(c3593.21,1588.62) 3593.21,1581.01 3925,1581 3990,1581 3995,1586 v1(3995,1600)
  Bottom Copper w8: v1(3995,1600) J1.B16@4015,1600
DOUT6_ADC_N: C100.1 U1.49 | length 754.5
  Top Copper w7: U1.49@3063.23,1227.36 3070.12,1227.36 3073.96,1231.2 3090.51,1231.2 3157.18,1231.2 ccw(c3157.18,1323) 3222.06,1258.06 ; 3222.09,1258.09 3364.66,1400.66 ccw(c3318.14,1447.18) 3383.93,1447.18 3383.93,1514.69 cw(c3538.24,1514.69) 3538.24,1669 3541.62,1669 cw(c3541.62,1648.71) 3555.44,1663.57 cw(c3541.62,1648.71) 3555.97,1663.06 C100.1@3559.03,1660
DOUT6_ADC_P: C98.1 U1.50 | length 754
  Top Copper w7: U1.50@3063.23,1247.05 3070.12,1247.05 3073.96,1243.2 3090.51,1243.2 3157.18,1243.2 ccw(c3157.18,1323) 3213.57,1266.54 ccw(c3157.18,1323) 3213.61,1266.58 3352.66,1405.63 ccw(c3306.14,1452.15) 3371.93,1452.15 3371.93,1514.69 cw(c3538.24,1514.69) 3538.24,1681 3541.62,1681 ccw(c3541.62,1701.3) 3555.44,1686.43 ccw(c3541.62,1701.3) 3555.97,1686.94 C98.1@3559.03,1690
DOUT6_FMC_N: C100.2 J1.A15 | length 503.4
  Top Copper w7: C100.2@3581.07,1660 3587.83,1666.76 cw(c3593.21,1661.39) 3593.21,1668.99 3970.03,1669 4040,1669 4045,1664 v1(4045,1650)
  Bottom Copper w8: v1(4045,1650) J1.A15@4065,1650
DOUT6_FMC_P: C98.2 J1.A14 | length 503.4
  Top Copper w7: C98.2@3581.07,1690 3587.83,1683.24 ccw(c3593.21,1688.62) 3593.21,1681.01 3975,1681 4040,1681 4045,1686 v1(4045,1700)
  Bottom Copper w8: v1(4045,1700) J1.A14@4065,1700
DOUT7_ADC_N: C104.1 U1.52 | length 775.1
  Top Copper w7: U1.52@3063.23,1286.42 3070.12,1286.42 3073.96,1290.26 3090.51,1290.26 3142.84,1290.26 ccw(c3142.84,1329.83) 3170.77,1301.8 ccw(c3142.84,1329.83) 3170.82,1301.85 3293.56,1424.59 ccw(c3239.38,1478.76) 3316,1478.76 3316,1554.11 ; 3316,1554.15 cw(c3429.66,1553.92) 3349.29,1634.29 3458.5,1743.5 cw(c3520.06,1681.94) 3520.06,1769 3541.62,1769 cw(c3541.62,1748.71) 3555.44,1763.57 cw(c3541.62,1748.71) 3555.97,1763.06 C104.1@3559.03,1760
DOUT7_ADC_P: C102.1 U1.53 | length 775.6
  Top Copper w7: U1.53@3063.23,1306.1 3070.12,1306.1 3073.96,1302.26 3090.51,1302.26 3142.84,1302.26 ccw(c3142.84,1329.83) 3162.32,1310.32 ; 3162.34,1310.34 3285.07,1433.07 ccw(c3239.38,1478.76) 3304,1478.76 3304,1554.1 cw(c3429.66,1553.92) 3304,1554.16 cw(c3429.66,1553.92) 3340.8,1642.77 3453.53,1755.5 cw(c3515.09,1693.94) 3515.09,1781 3541.62,1781 ccw(c3541.62,1801.3) 3555.44,1786.43 ccw(c3541.62,1801.3) 3555.97,1786.94 C102.1@3559.03,1790
DOUT7_FMC_N: C104.2 J1.B13 | length 453.4
  Top Copper w7: C104.2@3581.07,1760 3587.83,1766.76 cw(c3593.21,1761.39) 3593.21,1768.99 3920.03,1769 3990,1769 3995,1764 v1(3995,1750)
  Bottom Copper w8: v1(3995,1750) J1.B13@4015,1750
DOUT7_FMC_P: C102.2 J1.B12 | length 453.4
  Top Copper w7: C102.2@3581.07,1790 3587.83,1783.24 ccw(c3593.21,1788.62) 3593.21,1781.01 3990,1781 3995,1786 v1(3995,1800)
  Bottom Copper w8: v1(3995,1800) J1.B12@4015,1800
DVDD: C46.2 C122.2 C123.2 C124.2 C125.2 C126.2 C127.2 C128.2 C129.2 C130.2 C131.2 PP9.1 R26.2 R27.2 U1.3 U1.7 U1.9 U1.40 U1.42 U1.46 U1.54 U1.59 U10.D1 U10.D2 | length 1293
  Top Copper w8: U10.D2@753.43,1382.2 753.43,1395 759.13,1400.69 759.13,1408.4 773.08,1422.36 R26.2@780.79,1422.36 780.79,1393.82 U10.D1@769.18,1382.2
  Top Copper w9: C129.2@2880.16,1173.99 U1.40@2880.16,1201.77 v1(2880.16,1226.87) ; v1(2880.16,1522.23) U1.9@2880.16,1548.23 ; U1.9@2880.43,1548.46 C130.2@2880.43,1576.24 ; C127.2@2919.53,1173.99 U1.42@2919.53,1201.77 v1(2919.53,1226.87) ; v1(2919.53,1522.23) U1.7@2919.53,1548.23 ; U1.7@2919.8,1548.46 C126.2@2919.8,1576.24 ; C131.2@2998.25,1173.97 U1.46@2998.27,1201.77 v1(2998.27,1226.87) v1@2998.27,1227.77 ; v1(2998.27,1522.23) U1.3@2998.27,1548.23 C128.2@2998.27,1576.01 ; v1(3036,1325.79) U1.54@3063.23,1325.79 C125.2@3091.01,1325.79 ; v1@3040.98,1424.21 U1.59@3063.23,1424.21 3084.21,1424.21 3088.5,1428.5 C124.2@3091.01,1428.5
  Bottom Copper w9: v1@101.37,1349.12 219.53,1349.12 339.88,1469.47 v1(780.5,1469.47) ; v1(2880.16,1226.87) 2880.16,1215.84 C123.2@2882,1214 ; v1(3042,1428.2) 3043.72,1429.92 3056.21,1429.92 C122.2@3061,1434.71
  other v1: 2922.24,1178.73 100.46,1349.13 901.45,1413.63 921.45,1413.63 901.45,1433.63 921.45,1433.63
EXTCLK: C103.1 J4.1 | length 239.2
  Top Copper w5.5: v1(1691.27,2268.94) J4.1@1691.27,2367.94
  Bottom Copper w10: C103.1@1691.27,2128.73 v1(1691.27,2268.94)
FPGA_CORECLK_N: C138.2 J1.G7 | length 2632.5
  Layer 7 (SIG1) w4: v1(1624,1643.39) 1624,1645.71 1616.98,1652.74 1616.98,1905.05 1870.93,2159 2322,2159 2406,2075 2439,2042 2955.49,2042 2971.49,2042 cw(c2971.49,2035) 2978.49,2035 2978.49,2034.76 ccw(c2985.49,2034.76) 2992.49,2034.76 2992.49,2035 cw(c2999.49,2035) 2999.49,2042 3028.76,2042 3511.14,2042 3539.14,2070 3742.66,2070 3745,2067.66 v1(3745,2050)
  Bottom Copper w8: v1(3745,2050) J1.G7@3765,2050
  Bottom Copper w10: C138.2@1623.44,1624.1 1623.72,1624.38 1623.72,1643.11 v1(1624,1643.39)
FPGA_CORECLK_P: C137.2 J1.G6 | length 2632.5
  Layer 7 (SIG1) w4: v1(1599.96,1643.39) 1599.96,1645.71 1606.98,1652.74 1606.98,1909.2 1866.78,2169 2326.14,2169 2443.14,2052 3507,2052 3535,2080 3742.66,2080 3745,2082.34 v1(3745,2100)
  Bottom Copper w8: v1(3745,2100) J1.G6@3765,2100
  Bottom Copper w10: v1(1599.96,1643.39) 1600.2,1643.15 1600.2,1624.34 C137.2@1600.44,1624.1
FPGA_GBTCLK0_FMC_N: C136.2 J1.D5 | length 2874.3
  Layer 7 (SIG1) w4: v1@1565.83,1643.39 1565.83,1645.24 1558.33,1652.74 1558.33,1888.03 1861.3,2191 2338,2191 2456,2073 3471,2073 3568,2170 3762,2170 3778,2170 cw(c3778,2163) 3785,2163 3785,2162.4 ccw(c3792,2162.4) 3799,2162.4 3799,2163 cw(c3806,2163) 3806,2170 3821.57,2170 3892.66,2170 3895,2167.66 v1(3895,2150)
  Bottom Copper w8: v1(3895,2150) J1.D5@3915,2150
  Bottom Copper w10: C136.2@1564.39,1624.1 1564.63,1624.34 1564.63,1643.15 v1(1564.88,1643.39)
FPGA_GBTCLK0_FMC_P: C135.2 J1.D4 | length 2874.5
  Layer 7 (SIG1) w4: v1(1540.83,1643.39) 1540.83,1645.24 1548.33,1652.74 1548.33,1892.17 1857.16,2201 1858.89,2201 1859.89,2202 2341.14,2202 2460.14,2083 3466.86,2083 3563.86,2180 3892.66,2180 3895,2182.34 v1(3895,2200)
  Bottom Copper w8: v1(3895,2200) J1.D4@3915,2200
  Bottom Copper w10: v1(1540.83,1643.39) 1541.11,1643.11 1541.11,1624.38 C135.2@1541.39,1624.1
FPGA_GBTCLK1_FMC_N: C134.2 J1.B21 | length 2912.5
  Layer 7 (SIG1) w4: v1@1639.87,1086.14 1639.87,1083.82 1646.89,1076.8 1646.89,1063.79 1683.69,1027 1751,1027 1780,1056 1922.86,1056 1997.07,981.79 2000,978.86 2120,978.86 2125.86,984.72 2385,1243.86 2385,1431.09 2426.5,1472.59 2503.59,1472.59 2579,1548 3753,1548 3931,1370 3992.66,1370 3995,1367.66 v1(3995,1350)
  Bottom Copper w4: v1(3995,1350) 4014,1350 J1.B21@4015,1351
  Bottom Copper w10: v1(1638.91,1086.14) 1639.36,1086.59 1639.36,1107.1 C134.2@1639.81,1107.55
FPGA_GBTCLK1_FMC_P: C133.2 J1.B20 | length 2912.6
  Layer 7 (SIG1) w4: v1(1663.91,1086.14) 1663.91,1083.82 1656.89,1076.8 1656.89,1067.11 1687,1037 1746.86,1037 1775.86,1066 1789.8,1066 1819.87,1066 ccw(c1819.87,1073) 1826.87,1073 ; 1826.87,1073.04 cw(c1833.87,1073.04) 1840.87,1073.04 ; 1840.87,1073 ccw(c1847.87,1073) 1847.87,1066 1863.87,1066 1927,1066 2004.14,988.86 2115.86,988.86 2375,1248 2375,1435.23 2422.36,1482.59 2499.45,1482.59 2574.86,1558 3758,1558 3936,1380 3992.66,1380 3995,1382.34 v1(3995,1400)
  Bottom Copper w4: v1(3995,1400) 4014,1400 J1.B20@4015,1401
  Bottom Copper w10: C133.2@1662.82,1107.55 1663.36,1107 1663.36,1086.69 v1(1663.91,1086.14)
FPGA_SYSREF_N: J1.G10 R157.1 R161.1 | length 2593.5
  Layer 7 (SIG1) w4: v1@1741.95,1647.51 1741.95,1649.83 1734.93,1656.85 1734.93,1982.93 1735,1982.93 1882,2129.93 1882,2130 1956,2130 1972,2130 cw(c1972,2123) 1979,2123 1979,2122.33 ccw(c1986,2122.33) 1993,2122.33 1993,2123 cw(c2000,2123) 2000,2130 2017.61,2130 2304,2130 2427,2007 2905.86,2007 2993.93,1918.93 3012.86,1900 3661,1900 3681,1920 3742.66,1920 3745,1917.66 v1(3745,1900)
  Bottom Copper w4: v1(3745,1900) 3765,1900 J1.G10@3765,1901
  Bottom Copper w10: R157.1@1741.56,1624.1 1741.82,1624.36 1741.82,1647.25 v1(1742.08,1647.51)
FPGA_SYSREF_P: J1.G9 R158.1 R160.1 | length 2593.6
  Layer 7 (SIG1) w4: v1@1717.91,1647.51 1717.91,1649.83 1724.93,1656.85 1724.93,1987.07 1730.79,1992.93 1730.86,1992.93 1872,2134.07 1872,2134.14 1878.86,2141 1956,2141 2307.14,2141 2431.14,2017 2910,2017 3017,1910 3287,1910 3439.05,1910 3656.86,1910 3676.86,1930 3742.66,1930 3745,1932.34 v1(3745,1950)
  Bottom Copper w4: v1(3745,1950) 3765,1950 J1.G9@3765,1951
  Bottom Copper w10: v1(1718.03,1647.51) 1718.29,1647.25 1718.29,1624.36 R158.1@1718.56,1624.1
FTDI_SCL: J3.28 R91.1 | length 126.2
  Top Copper w8: J3.28@531.28,1666 531.28,1610.69 v1(531.43,1610.54)
  Bottom Copper w8: v1(531.43,1610.54) 570.28,1571.69 R91.1@570.28,1556
FTDI_SDA_READ: J3.34 R55.1 | length 87.2
  Top Copper w8: R55.1@467.85,1580.62 467.85,1602.68 472.22,1607.05 J3.34@472.22,1666
FTDI_SDA_WRITE: J3.30 R82.1 U26.1 | length 169.1
  Top Copper w6: J3.30@511.59,1666 511.59,1585.75 v1(513.27,1584.07)
  Bottom Copper w8: U26.1@481,1515.06 481,1522.02 482.91,1523.92 489.86,1523.92 513.27,1547.33 v1(513.27,1584.07)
